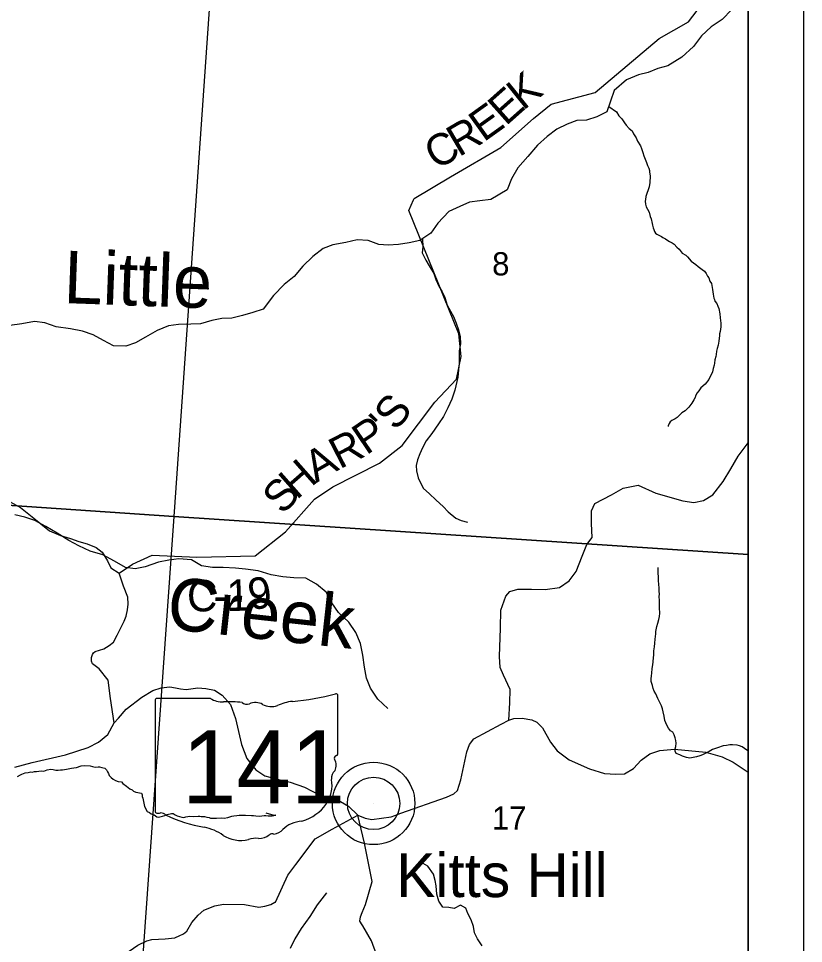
# Model space of a CAD drawing. Extents: x 0 to 34, y 0 to 22.
# Drawn here: x 7.584 to 9, y 17.554 to 19.223 of the extents above; entities that cross this region are included whole.
import ezdxf

# ---------------------------------------------------------------- set-up
doc = ezdxf.new("R2010")
doc.units = 0
for name, color, linetype in [('GM_X_Corporation', 7, 'Continuous'), ('GM_X_County_Road', 7, 'Continuous'), ('GM_X_County_Road_Text', 7, 'Continuous'), ('GM_X_Minor_River', 7, 'Continuous'), ('GM_X_Minor_River_Text', 7, 'Continuous'), ('GM_X_Section_Text', 7, 'Continuous'), ('GM_X_State_Location', 7, 'Continuous'), ('GM_X_State_Route', 7, 'Continuous'), ('GM_X_State_Shield', 7, 'Continuous'), ('GM_X_Township_Road', 7, 'Continuous'), ('GM_X_Unincorporated', 7, 'Continuous'), ('GM_X_Unincorporated_Location', 7, 'Continuous'), ('GM_X_Unincorporated_Text', 7, 'Continuous'), ('SH_Data', 7, 'Continuous')]:
    doc.layers.add(name, color=color, linetype=linetype)

msp = doc.modelspace()

# ---------------------------------------------------------------- linework, layer by layer
at = {"layer": 'GM_X_Corporation'}
for points in [[(3.3441, 14.1), (8.9, 14.1), (8.9, 20.9), (2.1, 20.9), (2.1, 16.1353), (2.1457, 16.065), (2.3447, 15.6926), (2.4297, 15.5215), (2.465, 15.4504), (2.4884, 15.4033), (2.5769, 15.2135), (2.7849, 14.8403), (2.8931, 14.6544), (3.0297, 14.4867), (3.1386, 14.3654), (3.228, 14.2415)], [(8.9, 16.2015), (8.9, 20.2763), (8.59, 20.3005), (8.3805, 20.3169), (8.0028, 20.34), (6.9032, 20.4198), (6.8961, 20.3303), (6.835, 19.4037), (6.824, 19.3005), (6.7876, 18.7583), (6.7629, 18.3924), (6.7536, 18.2991), (6.7043, 17.4985), (6.6962, 17.3669), (6.6852, 17.2401), (6.6249, 16.3344), (7.5782, 16.28), (7.7162, 16.2721), (7.873, 16.2628)], [(7.9347, 19.3346), (7.864, 18.3242), (6.7676, 18.3985), (6.8303, 19.3047), (6.8376, 19.4096)], [(8.9, 18.2556), (8.9, 19.2681), (7.9347, 19.3346), (7.864, 18.3242)], [(6.7676, 18.3985), (7.864, 18.3242), (7.7921, 17.3025), (6.6999, 17.3699), (6.7615, 18.3053)], [(8.9, 17.3437), (8.9, 18.2556), (7.864, 18.3242), (7.7921, 17.3025), (8.8926, 17.2358)]]:
    msp.add_lwpolyline(points, close=True, dxfattribs=at)
at = {"layer": 'GM_X_County_Road'}
for points in [[(7.7563, 17.9516), (7.75, 17.9954), (7.7459, 18.0284), (7.7294, 18.0492), (7.7175, 18.0582), (7.7158, 18.0632), (7.7155, 18.0696), (7.7174, 18.0748), (7.7192, 18.0783), (7.7226, 18.0803), (7.7382, 18.0854), (7.7473, 18.0914), (7.7552, 18.0973), (7.762, 18.1098), (7.7745, 18.1349), (7.7783, 18.1439), (7.7808, 18.1553), (7.7817, 18.1657), (7.7811, 18.1782), (7.7733, 18.1983), (7.7653, 18.2219), (7.7898, 18.2379), (7.8252, 18.2542), (7.9055, 18.2504), (8.0107, 18.2532), (8.0658, 18.2962), (8.1178, 18.3552), (8.151, 18.3776), (8.235, 18.4201), (8.2758, 18.4524), (8.3352, 18.5301), (8.3743, 18.5719), (8.3827, 18.6126), (8.3782, 18.6537), (8.2881, 18.876), (8.2966, 18.8955), (8.2975, 18.898), (8.3632, 18.9371), (8.4539, 18.9899), (8.5131, 19.0421), (8.5448, 19.0682), (8.6241, 19.0891), (8.7399, 19.1866), (8.7925, 19.2167), (8.824, 19.2581)], [(8.4685, 17.9564), (8.4704, 17.9878), (8.4708, 18.0118), (8.4587, 18.0376), (8.453, 18.0517), (8.4515, 18.0711), (8.4535, 18.1228), (8.4539, 18.1551), (8.463, 18.1802), (8.4702, 18.1885), (8.4847, 18.1927), (8.5093, 18.1931), (8.534, 18.1923), (8.5599, 18.1961), (8.5773, 18.2079), (8.5899, 18.2246), (8.6009, 18.2523), (8.6093, 18.2736), (8.6188, 18.2861), (8.6177, 18.3112), (8.6177, 18.334), (8.6234, 18.3477), (8.6538, 18.3633), (8.6747, 18.375), (8.7017, 18.3803), (8.7339, 18.3663), (8.7826, 18.3522), (8.8023, 18.3495), (8.8194, 18.3526), (8.8365, 18.3632), (8.8551, 18.3871), (8.8688, 18.4099), (8.8821, 18.4331), (8.9, 18.4569)], [(8.0843, 17.6958), (8.1193, 17.7424), (8.1499, 17.7597), (8.1964, 17.7853)], [(8.2039, 17.5873), (8.2, 17.594), (8.2009, 17.6016), (8.204, 17.6097), (8.21, 17.6242), (8.2218, 17.6657), (8.2079, 17.7348), (8.1964, 17.7853)], [(8.0464, 17.6279), (8.0473, 17.6284), (8.0701, 17.6769), (8.0843, 17.6958)], [(7.866, 17.564), (7.867, 17.5641), (7.874, 17.5671), (7.8815, 17.5709), (7.8874, 17.5757), (7.8964, 17.5913), (7.9083, 17.6047), (7.9182, 17.6136), (7.9383, 17.6215), (7.9539, 17.6245), (7.9915, 17.6241), (8.0178, 17.619), (8.0283, 17.6209), (8.039, 17.6241), (8.0464, 17.6279)], [(8.2298, 17.5335), (8.2208, 17.5581), (8.2049, 17.5857), (8.2039, 17.5873)], [(7.5153, 17.4745), (7.5203, 17.488), (7.5383, 17.5171), (7.5434, 17.5211), (7.5527, 17.523), (7.5599, 17.5233), (7.5721, 17.5199), (7.5831, 17.5133), (7.5993, 17.4944), (7.6154, 17.4786), (7.6196, 17.4761), (7.6284, 17.4748), (7.6424, 17.475), (7.6731, 17.4871), (7.7014, 17.5056), (7.7298, 17.5182), (7.7491, 17.5284), (7.7756, 17.534), (7.7991, 17.5506), (7.8152, 17.5584), (7.8244, 17.561), (7.8484, 17.562), (7.866, 17.564)]]:
    msp.add_lwpolyline(points, dxfattribs=at)
at = {"layer": 'GM_X_Minor_River'}
for points in [[(8.8709, 19.2387), (8.8534, 19.2205), (8.8337, 19.2077), (8.8162, 19.1911), (8.8018, 19.1721), (8.7805, 19.1525), (8.7555, 19.1374), (8.7373, 19.1321), (8.7199, 19.1253), (8.7024, 19.1208), (8.6805, 19.1118), (8.6585, 19.0929), (8.6455, 19.0542), (8.6273, 19.0452), (8.6083, 19.0391), (8.5909, 19.0384), (8.5735, 19.0317), (8.5553, 19.0226), (8.5378, 19.0098), (8.5204, 18.9939), (8.5029, 18.9734), (8.4847, 18.953), (8.4733, 18.9333), (8.4656, 18.9136), (8.4361, 18.8962), (8.4164, 18.8933), (8.3974, 18.891), (8.38, 18.8835), (8.3603, 18.8744)], [(8.6487, 19.0639), (8.6625, 19.0544), (8.6669, 19.0467), (8.6725, 19.0413), (8.6773, 19.0344), (8.6802, 19.0298), (8.6858, 19.024), (8.6907, 19.0197), (8.6936, 19.0147), (8.698, 19.0071), (8.7006, 19.0013), (8.7057, 18.9929), (8.7075, 18.9879), (8.7104, 18.981), (8.7122, 18.9745), (8.7159, 18.9657), (8.7166, 18.963), (8.7184, 18.9573), (8.7209, 18.9527), (8.722, 18.9485), (8.7223, 18.9458), (8.7233, 18.9382), (8.7231, 18.9268), (8.7215, 18.9189), (8.7199, 18.9136), (8.7175, 18.9068), (8.7159, 18.9011), (8.715, 18.8958), (8.7146, 18.8932), (8.7152, 18.8878), (8.7163, 18.8829), (8.7185, 18.8787), (8.7214, 18.8729), (8.7232, 18.8653), (8.7254, 18.8611), (8.7268, 18.8527), (8.7278, 18.8496), (8.7289, 18.8447), (8.7303, 18.8416), (8.731, 18.8382), (8.7329, 18.8351), (8.7355, 18.8332), (8.7381, 18.832), (8.7438, 18.8292), (8.7464, 18.8277), (8.7509, 18.8249), (8.7535, 18.823), (8.758, 18.8202), (8.7633, 18.8175), (8.7666, 18.8151), (8.7718, 18.8101), (8.7756, 18.8066), (8.7811, 18.7993), (8.7875, 18.7954), (8.7908, 18.7923), (8.7975, 18.7846), (8.8057, 18.7784), (8.8102, 18.7749), (8.817, 18.7698), (8.8214, 18.7667), (8.8244, 18.7625), (8.8266, 18.7575), (8.8292, 18.7548), (8.831, 18.7487), (8.8339, 18.7445), (8.8356, 18.7334), (8.837, 18.725), (8.838, 18.7182), (8.8395, 18.7155), (8.8402, 18.7128), (8.8435, 18.7086), (8.8453, 18.7036), (8.8472, 18.6994), (8.8489, 18.6895), (8.8499, 18.6823), (8.8509, 18.6727), (8.8507, 18.6663), (8.8495, 18.6576), (8.8486, 18.6538), (8.8486, 18.6507), (8.8473, 18.6405), (8.846, 18.6333), (8.844, 18.6269), (8.8432, 18.6223), (8.8423, 18.6166), (8.8418, 18.6125), (8.8402, 18.6068), (8.8394, 18.6007), (8.8389, 18.5969), (8.8373, 18.5913), (8.8357, 18.5852), (8.8345, 18.5822), (8.8318, 18.5769), (8.829, 18.5713), (8.8224, 18.5626), (8.8147, 18.5559), (8.8112, 18.551), (8.8085, 18.5473), (8.8054, 18.5416), (8.8046, 18.539)], [(8.3603, 18.8744), (8.3406, 18.8533), (8.3276, 18.8351), (8.3079, 18.8222), (8.289, 18.8177), (8.2693, 18.8148), (8.2511, 18.8133), (8.2337, 18.8149), (8.2148, 18.8218), (8.1951, 18.8233), (8.1747, 18.8181), (8.1512, 18.8144), (8.1338, 18.8076), (8.1148, 18.7932), (8.0966, 18.7758), (8.0814, 18.7569), (8.0632, 18.7425), (8.0442, 18.7229), (8.0252, 18.6979), (8.007, 18.6918), (7.9881, 18.6866), (7.9691, 18.6821), (7.9509, 18.6814), (7.9328, 18.6777), (7.9123, 18.6716), (7.8949, 18.6709), (7.8729, 18.6702), (7.8548, 18.668), (7.8343, 18.6597), (7.8131, 18.6477), (7.7949, 18.6371), (7.7774, 18.6311), (7.7555, 18.6319), (7.7374, 18.6418), (7.7185, 18.6517), (7.6996, 18.6586), (7.6776, 18.6625), (7.6519, 18.6663), (7.6315, 18.6732), (7.6126, 18.6756), (7.5898, 18.6718), (7.5686, 18.6689)], [(8.3125, 18.8252), (8.3132, 18.8105), (8.3121, 18.7995), (8.3189, 18.7867), (8.3246, 18.776), (8.3329, 18.7624), (8.3367, 18.7514), (8.342, 18.7396), (8.348, 18.7294), (8.3529, 18.7192), (8.3575, 18.7055), (8.3631, 18.6945), (8.3688, 18.6847), (8.3737, 18.6726), (8.3779, 18.6608), (8.3809, 18.6483), (8.3813, 18.6358), (8.379, 18.6229), (8.379, 18.6005), (8.3779, 18.5888), (8.3764, 18.5755), (8.3711, 18.552), (8.3654, 18.5357), (8.3586, 18.5202), (8.3506, 18.5046), (8.3415, 18.4914), (8.3298, 18.4739), (8.3192, 18.4607), (8.3128, 18.4478), (8.3078, 18.4371), (8.3037, 18.4262), (8.3014, 18.4163), (8.3018, 18.4061), (8.3048, 18.3939), (8.309, 18.3845), (8.3146, 18.3746), (8.3248, 18.3655), (8.3377, 18.3534), (8.3498, 18.342), (8.3589, 18.3325), (8.3729, 18.3208), (8.3827, 18.317), (8.3937, 18.3139), (8.3937, 18.3136)], [(8.8046, 18.539), (8.8022, 18.5345), (8.7983, 18.5285), (8.7968, 18.5258), (8.7933, 18.5213), (8.7863, 18.5146), (8.7806, 18.5113), (8.7775, 18.5079), (8.7721, 18.5027), (8.7683, 18.5001), (8.7626, 18.4975), (8.7595, 18.4949), (8.7579, 18.4915), (8.7559, 18.4874), (8.7557, 18.4862)], [(8.2501, 17.9777), (8.2319, 17.9944), (8.2191, 18.0142), (8.2116, 18.0324), (8.2079, 18.0522), (8.2049, 18.0735), (8.2012, 18.0947), (8.1922, 18.1145), (8.1801, 18.1335), (8.1613, 18.151), (8.1492, 18.1685), (8.1387, 18.1875), (8.1213, 18.202), (8.1024, 18.2127), (8.0805, 18.2135), (8.0608, 18.2151), (8.0396, 18.2189), (8.0162, 18.2258), (7.9935, 18.2289), (7.9753, 18.2305), (7.9533, 18.2321), (7.9337, 18.2321), (7.914, 18.2352), (7.8959, 18.2459), (7.8732, 18.2475), (7.855, 18.2453), (7.8368, 18.2415), (7.8126, 18.2332), (7.7944, 18.2295), (7.777, 18.2318), (7.7573, 18.2433), (7.7362, 18.2547), (7.7135, 18.2616), (7.6931, 18.2708), (7.6749, 18.2807), (7.6538, 18.2937), (7.6334, 18.3059), (7.6137, 18.3166), (7.5956, 18.3227), (7.5774, 18.3273)], [(8.9, 17.9012), (8.898, 17.9023), (8.8938, 17.9054), (8.8893, 17.9082), (8.8845, 17.9105), (8.8803, 17.9114), (8.872, 17.9123), (8.8671, 17.9123), (8.8614, 17.9109), (8.8553, 17.9099), (8.8446, 17.9063), (8.8359, 17.9034), (8.8297, 17.9), (8.8248, 17.8978), (8.8179, 17.8938), (8.8133, 17.8923), (8.8072, 17.8902), (8.8008, 17.8891), (8.7947, 17.8877), (8.789, 17.889), (8.7815, 17.8914), (8.777, 17.8937), (8.7706, 17.8961), (8.7684, 17.9007), (8.7688, 17.9049), (8.7697, 17.909), (8.7705, 17.9151), (8.7699, 17.9197), (8.7684, 17.9246), (8.767, 17.93), (8.7641, 17.935), (8.7599, 17.937), (8.7566, 17.9423), (8.7537, 17.9473), (8.75, 17.9557), (8.7487, 17.9638), (8.7469, 17.9718), (8.7455, 17.9771), (8.7441, 17.9821), (8.74, 17.9894), (8.7375, 17.9959), (8.7335, 18.0039), (8.7309, 18.0089), (8.7291, 18.0139), (8.7277, 18.0192), (8.7255, 18.0261), (8.7252, 18.031), (8.7257, 18.0364), (8.7262, 18.0413), (8.7271, 18.0496), (8.7283, 18.0565), (8.7288, 18.0618), (8.7293, 18.0694), (8.7298, 18.0735), (8.7303, 18.0815), (8.7312, 18.0891), (8.7316, 18.0952), (8.7322, 18.1028), (8.7335, 18.1122), (8.7335, 18.1164), (8.7352, 18.1255), (8.7372, 18.1316), (8.7388, 18.1384), (8.7401, 18.1433), (8.7406, 18.1498), (8.7403, 18.1593), (8.7404, 18.1638), (8.7401, 18.1691), (8.7402, 18.1733), (8.7399, 18.179), (8.74, 18.1844), (8.7397, 18.1889), (8.7399, 18.1961), (8.7392, 18.2007), (8.7386, 18.2091), (8.7383, 18.2163), (8.738, 18.2205), (8.7381, 18.2273), (8.7378, 18.2319)], [(7.5824, 17.8546), (7.5874, 17.8576), (7.5901, 17.859), (7.5962, 17.8612), (7.6015, 17.8619), (7.606, 17.863), (7.6087, 17.8629), (7.6129, 17.864), (7.6167, 17.8639), (7.6208, 17.8642), (7.6246, 17.8649), (7.6299, 17.8645), (7.636, 17.867), (7.6425, 17.868), (7.6466, 17.8672), (7.6515, 17.8664), (7.6553, 17.8663), (7.6595, 17.8666), (7.6633, 17.8666), (7.6667, 17.8673), (7.6705, 17.8683), (7.6796, 17.8697), (7.6838, 17.8704), (7.6888, 17.8714), (7.6968, 17.8743), (7.7024, 17.8746), (7.7134, 17.8744), (7.7176, 17.8732), (7.7225, 17.872), (7.7278, 17.8723), (7.7304, 17.8723), (7.7346, 17.871), (7.7395, 17.8698), (7.7425, 17.8671), (7.7443, 17.8633), (7.7461, 17.8602), (7.7476, 17.8568), (7.7513, 17.8533), (7.755, 17.8502), (7.7588, 17.8474)], [(7.7588, 17.8474), (7.7637, 17.8458), (7.7701, 17.845), (7.7723, 17.8423), (7.7791, 17.8376), (7.7821, 17.8349), (7.785, 17.8326), (7.7888, 17.831), (7.7914, 17.8283), (7.7955, 17.8267), (7.8061, 17.825), (7.8068, 17.8219), (7.8071, 17.8189), (7.8082, 17.8158), (7.81, 17.807), (7.8114, 17.8009), (7.8161, 17.7917), (7.8203, 17.7898), (7.8233, 17.7874), (7.8289, 17.7854), (7.8334, 17.7819), (7.8368, 17.7815), (7.844, 17.7833), (7.8482, 17.7843), (7.852, 17.7862), (7.86, 17.788), (7.8627, 17.7883), (7.8668, 17.7859), (7.8705, 17.784), (7.8785, 17.7816), (7.8822, 17.7811), (7.8857, 17.7822), (7.8933, 17.7832), (7.8993, 17.7827), (7.908, 17.7833), (7.9111, 17.7833), (7.9137, 17.7829), (7.9194, 17.7828), (7.9235, 17.7816), (7.9277, 17.7807), (7.9303, 17.7799), (7.9345, 17.7795), (7.9409, 17.7794), (7.9508, 17.78), (7.9549, 17.7799), (7.9618, 17.7809), (7.9686, 17.7831), (7.9724, 17.7838), (7.9781, 17.7844), (7.9823, 17.7851), (7.988, 17.785), (7.9933, 17.7853), (8.0043, 17.7844), (8.0077, 17.7843), (8.0122, 17.7839), (8.019, 17.7834), (8.0232, 17.7837), (8.0274, 17.7844), (8.0304, 17.7843), (8.0346, 17.7839), (8.0414, 17.7841), (8.0444, 17.7845), (8.0482, 17.7848), (8.0452, 17.7844), (8.0305, 17.7885)], [(8.4204, 17.5496), (8.4117, 17.5621), (8.4064, 17.5727), (8.4045, 17.5841), (8.4004, 17.5962), (8.3947, 17.6076), (8.3909, 17.6171), (8.3811, 17.6227), (8.3701, 17.6167), (8.3602, 17.6182), (8.3496, 17.6193), (8.3421, 17.6299), (8.3387, 17.6428), (8.3375, 17.6576), (8.3357, 17.6675), (8.3326, 17.6785), (8.3224, 17.6933), (8.3137, 17.6978)], [(8.1393, 17.6448), (8.1226, 17.6235), (8.1096, 17.6023), (8.0937, 17.5804), (8.0823, 17.5622), (8.0739, 17.5447)]]:
    msp.add_lwpolyline(points, dxfattribs=at)
at = {"layer": 'GM_X_State_Route'}
for points in [[(7.5776, 17.8717), (7.6084, 17.8801), (7.6688, 17.8942), (7.7095, 17.907), (7.7282, 17.917), (7.745, 17.9305), (7.7563, 17.9516), (7.7643, 17.9603), (7.7782, 17.9761), (7.8064, 17.9978), (7.8263, 18.0101), (7.8415, 18.0148), (7.8567, 18.0169), (7.8673, 18.0149), (7.876, 18.0133), (7.8865, 18.012), (7.9074, 18.0148), (7.9222, 18.0139), (7.9373, 18.0107), (7.9516, 18.0018), (7.9662, 17.9846), (7.9757, 17.9598), (7.9865, 17.9126), (7.996, 17.8874), (8.0121, 17.8671), (8.0283, 17.8563), (8.0554, 17.8488), (8.074, 17.8448), (8.1, 17.8354), (8.1278, 17.821), (8.1475, 17.8143), (8.1648, 17.8096), (8.1795, 17.8014), (8.1964, 17.7853), (8.2092, 17.7798), (8.2216, 17.7774), (8.2562, 17.7823), (8.2626, 17.7846), (8.2739, 17.7885)], [(8.2739, 17.7885), (8.3559, 17.8173), (8.3692, 17.8236), (8.3761, 17.8296), (8.3816, 17.8489), (8.3928, 17.8992), (8.3975, 17.9128), (8.4056, 17.9226), (8.4548, 17.9494), (8.4685, 17.9564), (8.4773, 17.9594), (8.4928, 17.9603), (8.5098, 17.9571), (8.5189, 17.9532), (8.5294, 17.9428), (8.5438, 17.9168), (8.5554, 17.9012), (8.5772, 17.885), (8.6141, 17.8686), (8.6413, 17.8603), (8.6617, 17.8589), (8.6772, 17.8599), (8.6933, 17.8692), (8.7071, 17.8842), (8.7231, 17.8955), (8.7406, 17.9017), (8.7672, 17.9044), (8.8236, 17.8985), (8.853, 17.8902), (8.8733, 17.8805), (8.9, 17.8628)]]:
    msp.add_lwpolyline(points, dxfattribs=at)
at = {"layer": 'GM_X_State_Shield'}
for p, q in [((7.8304, 17.9922), (7.8304, 17.7921)), ((7.9302, 17.9957), (7.8337, 17.9957)), ((8.16, 17.896), (8.16, 18.0006)), ((8.16, 17.896), (8.16, 17.896))]:
    msp.add_line(p, q, dxfattribs=at)
for centre, major_axis, start_param, end_param in [((7.8342, 17.9927), (0.00382, 0), 1.712693, 3.28349), ((7.9532, 18.0189), (0.037, 0), 4.042523, 4.731795), ((8.0426, 18.2685), (0.3495, 0), 4.814394, 5.042369), ((8.1564, 18.0011), (0.00367, 0), 6.141152, 7.989035), ((7.9655, 17.8833), (0.133, 0), 1.404758, 1.657858), ((7.9956, 17.9937), (0.0107, 0), 3.836095, 5.185415), ((8.0113, 17.9706), (0.0222, 0), 0.950623, 2.079405), ((8.04, 18.0023), (0.0267, 0), 4.081561, 5.145723), ((8.0872, 17.9346), (0.0703, 0), 1.699011, 2.107814), ((8.1592, 17.8883), (0.00568, 0), 1.883978, 3.671073), ((8.1561, 17.8956), (0.00393, 0), 5.05454, 6.418171), ((8.123, 17.875), (0.0341, 0), 5.934695, 6.695948), ((8.1732, 17.8522), (0.0248, 0), 2.387724, 3.262537), ((8.0622, 17.8388), (0.0874, 0), 5.101752, 6.440018), ((7.8342, 17.7917), (0.00385, 0), 3.00124, 4.508301), ((7.8348, 17.8122), (0.0294, 0), 4.665946, 4.897461), ((7.8408, 17.7806), (0.0106, 0), 0.519207, 1.627899), ((7.9747, 17.9604), (0.2524, 0), 4.195997, 4.488961), ((7.8994, 17.7022), (0.079, 0), 0.823519, 1.323587), ((8.0384, 17.7727), (0.0282, 0), 4.937069, 5.64225), ((8.099, 17.7359), (0.0479, 0), 1.647645, 2.488434), ((7.9848, 17.7796), (0.0501, 0), 4.026481, 4.996735), ((8.0138, 17.7104), (0.0412, 0), 1.495662, 1.94098), ((8.0174, 17.7646), (0.0267, 0), 4.691044, 5.507374), ((8.0416, 17.7452), (0.00752, 0), 1.147584, 2.315152)]:
    msp.add_ellipse(centre, major_axis=major_axis, ratio=0.8, start_param=start_param, end_param=end_param, dxfattribs=at)
at = {"layer": 'GM_X_Township_Road'}
msp.add_lwpolyline([(7.3446, 18.3224), (7.3577, 18.3221), (7.3765, 18.3175), (7.3969, 18.3146), (7.4082, 18.3146), (7.4559, 18.3303), (7.4825, 18.3368), (7.5007, 18.3482), (7.5174, 18.3512), (7.5478, 18.3531), (7.5679, 18.3512), (7.5877, 18.3405), (7.6089, 18.3234), (7.6401, 18.2983), (7.6598, 18.2896), (7.678, 18.2842), (7.6928, 18.2789), (7.7076, 18.2747), (7.7243, 18.2683), (7.735, 18.2599), (7.7445, 18.2439), (7.7505, 18.2314), (7.7653, 18.2219)], dxfattribs=at)
at = {"layer": 'GM_X_Unincorporated'}
for radius in [0.0744, 0.0472]:
    msp.add_circle((8.2246, 17.8063), radius, dxfattribs=at)
at = {"layer": 'GM_X_Unincorporated_Location'}
msp.add_line((8.2246, 17.8063), (8.2246, 17.8063), dxfattribs=at)
at = {"layer": 'SH_Data'}
for p, q in [((9, 21), (9, 14)), ((8.9, 20.9), (8.9, 14.1))]:
    msp.add_line(p, q, dxfattribs=at)

# ---------------------------------------------------------------- texts
at = {"layer": 'GM_X_County_Road_Text'}
for s, rotation, p in [('K', 38.7171, (8.494, 19.0553)), ('E', 41.6719, (8.4629, 19.0275)), ('E', 35.6256, (8.4232, 18.9987)), ('R', 30.4997, (8.3784, 18.9719)), ('C', 30.0879, (8.3376, 18.9483)), ('S', 50.9804, (8.265, 18.4767)), ("'", 47.5197, (8.2541, 18.4647)), ('P', 34.0733, (8.2113, 18.4337)), ('R', 27.1995, (8.1634, 18.4086)), ('A', 29.7834, (8.1206, 18.384)), ('H', 41.3998, (8.0856, 18.3528)), ('S', 48.1143, (8.0612, 18.3255)), ('C', 359.5746, (7.8877, 18.153)), ('1', 1.4547, (7.9598, 18.1532)), ('9', 8.5759, (8.0024, 18.1548)), ('-', 1.3403, (7.9363, 18.1526))]:
    msp.add_text(s, height=0.0568, rotation=rotation, dxfattribs=at).set_placement(p)
at = {"layer": 'GM_X_Minor_River_Text'}
for s, rotation, p in [('Little', 357.9213, (7.6644, 18.7092)), ('Creek', 353.7555, (7.8489, 18.1219))]:
    msp.add_text(s, height=0.09469, rotation=rotation, dxfattribs=at).set_placement(p)
at = {"layer": 'GM_X_Section_Text'}
for s, height, p in [('8', 0.0419, (8.4384, 18.759)), ('17', 0.04186, (8.438, 17.7592))]:
    msp.add_text(s, height=height, rotation=0, dxfattribs=at).set_placement(p)
at = {"layer": 'GM_X_State_Location'}
for s in ['s', 'r']:
    msp.add_text(s, height=0.000189, dxfattribs=at).set_placement((7.9915, 17.8789))
msp.add_text('141', height=0.000189, rotation=0, dxfattribs=at).set_placement((7.9247, 17.8651))
at = {"layer": 'GM_X_State_Shield'}
msp.add_text('141', height=0.13184, dxfattribs=at).set_placement((7.879, 17.8062))
at = {"layer": 'GM_X_Unincorporated_Text'}
msp.add_text('Kitts Hill', height=0.07898, rotation=0, dxfattribs=at).set_placement((8.2655, 17.6373))

doc.saveas('drawing.dxf')
